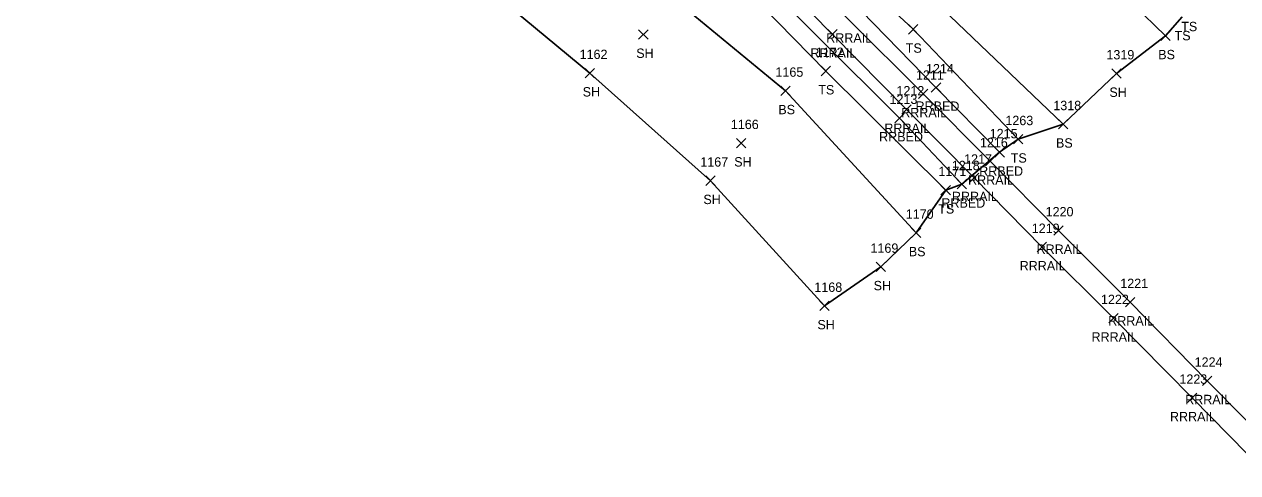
# Model space of a CAD drawing. Extents: x 1679360 to 1685861, y 903420 to 905946.
# Drawn here: x 1679830.3 to 1680089.3, y 903736.5 to 903832.2 of the extents above; entities that cross this region are included whole.
import ezdxf

# ---------------------------------------------------------------- set-up
doc = ezdxf.new("R2010")
doc.units = 0
for name, color, linetype in [('L_A', 7, 'Continuous'), ('L_I', 7, 'Continuous'), ('L_TIC', 7, 'Continuous'), ('LELB', 7, 'Continuous'), ('LSOGP', 7, 'Continuous'), ('R_A', 7, 'Continuous'), ('R_I', 7, 'Continuous'), ('R_TIC', 7, 'Continuous'), ('RR', 7, 'Continuous'), ('RRB', 7, 'Continuous')]:
    doc.layers.add(name, color=color, linetype=linetype)

msp = doc.modelspace()

# ---------------------------------------------------------------- linework, layer by layer
at = {"layer": 'L_TIC'}
for points in [[(1679961.47, 903829.04), (1679963.47, 903831.04)], [(1679963.47, 903829.04), (1679961.47, 903831.04)], [(1680019.07, 903830.14), (1680021.07, 903832.14)], [(1680021.07, 903830.14), (1680019.07, 903832.14)], [(1680072.91, 903828.75), (1680074.91, 903830.75)], [(1680074.91, 903828.75), (1680072.91, 903830.75)], [(1680000.4, 903821.24), (1680002.4, 903823.24)], [(1680002.4, 903821.24), (1680000.4, 903823.24)], [(1679950.04, 903820.8), (1679952.04, 903822.8)], [(1679952.04, 903820.8), (1679950.04, 903822.8)], [(1680062.45, 903820.72), (1680064.45, 903822.72)], [(1680064.45, 903820.72), (1680062.45, 903822.72)], [(1679991.84, 903817.01), (1679993.84, 903819.01)], [(1679993.84, 903817.01), (1679991.84, 903819.01)], [(1680051.1, 903809.88), (1680053.1, 903811.88)], [(1680053.1, 903809.88), (1680051.1, 903811.88)], [(1679982.38, 903805.85), (1679984.38, 903807.85)], [(1679984.38, 903805.85), (1679982.38, 903807.85)], [(1680041.48, 903806.68), (1680043.48, 903808.68)], [(1680043.48, 903806.68), (1680041.48, 903808.68)], [(1679975.8, 903797.83), (1679977.8, 903799.83)], [(1679977.8, 903797.83), (1679975.8, 903799.83)], [(1680026, 903795.8), (1680028, 903797.8)], [(1680028, 903795.8), (1680026, 903797.8)], [(1680019.69, 903786.69), (1680021.69, 903788.69)], [(1680021.69, 903786.69), (1680019.69, 903788.69)], [(1680012.13, 903779.43), (1680014.13, 903781.43)], [(1680014.13, 903779.43), (1680012.13, 903781.43)], [(1680000.15, 903771.09), (1680002.15, 903773.09)], [(1680002.15, 903771.09), (1680000.15, 903773.09)]]:
    msp.add_lwpolyline(points, dxfattribs=at)
at = {"layer": 'LELB'}
for points in [[(1680042.48, 903807.68), (1680020.07, 903831.14), (1679994.57, 903854.85), (1679973.52, 903877.19), (1679947.49, 903902.98), (1679918.08, 903936.81), (1679895.51, 903960.77), (1679875.1, 903984.26)], [(1679894.89, 903975.93), (1679910.27, 903960.99), (1679935.15, 903935.63), (1679969.34, 903902.55), (1679995.86, 903870.36), (1680023.14, 903838.66), (1680052.1, 903810.88)], [(1679854.83, 903964.92), (1679872.81, 903942.29), (1679891.12, 903918.82), (1679918.93, 903890.39), (1679939.76, 903869.14), (1679968.6, 903838.01), (1679992.84, 903818.01), (1680020.69, 903787.69)], [(1680027, 903796.8), (1680001.4, 903822.24), (1679984.38, 903839.7), (1679957.18, 903867.74), (1679928.2, 903894.12), (1679909.11, 903915.88), (1679887.98, 903941.49), (1679868.32, 903960.05)], [(1680073.91, 903829.75), (1680039.44, 903863.28), (1680011.71, 903891.77), (1679980.2, 903922.91), (1679955.89, 903942.39), (1679970.51, 903943.92), (1679984.54, 903937.24)]]:
    msp.add_lwpolyline(points, dxfattribs=at)
at = {"layer": 'LSOGP'}
msp.add_lwpolyline([(1679920.81, 903846.9), (1679951.04, 903821.8), (1679976.8, 903798.83), (1680001.15, 903772.09), (1680013.13, 903780.43), (1680020.69, 903787.69), (1680027, 903796.8), (1680030.44, 903798.07), (1680038.52, 903804.88), (1680042.48, 903807.68), (1680052.1, 903810.88), (1680063.45, 903821.72), (1680073.91, 903829.75), (1680077.44, 903833.8)], dxfattribs=at)
at = {"layer": 'R_TIC'}
for points in [[(1680001.83, 903829.07), (1680003.83, 903831.07)], [(1680003.83, 903829.07), (1680001.83, 903831.07)], [(1680021.22, 903816.37), (1680023.22, 903818.37)], [(1680023.22, 903816.37), (1680021.22, 903818.37)], [(1680023.93, 903817.74), (1680025.93, 903819.74)], [(1680025.93, 903817.74), (1680023.93, 903819.74)], [(1680016.14, 903811.2), (1680018.14, 903813.2)], [(1680018.14, 903811.2), (1680016.14, 903813.2)], [(1680017.62, 903813.03), (1680019.62, 903815.03)], [(1680019.62, 903813.03), (1680017.62, 903815.03)], [(1680037.52, 903803.88), (1680039.52, 903805.88)], [(1680039.52, 903803.88), (1680037.52, 903805.88)], [(1680035.49, 903801.97), (1680037.49, 903803.97)], [(1680037.49, 903801.97), (1680035.49, 903803.97)], [(1680032.05, 903798.46), (1680034.05, 903800.46)], [(1680034.05, 903798.46), (1680032.05, 903800.46)], [(1680029.44, 903797.07), (1680031.44, 903799.07)], [(1680031.44, 903797.07), (1680029.44, 903799.07)], [(1680050.11, 903787.21), (1680052.11, 903789.21)], [(1680052.11, 903787.21), (1680050.11, 903789.21)], [(1680046.5, 903783.67), (1680048.5, 903785.67)], [(1680048.5, 903783.67), (1680046.5, 903785.67)], [(1680065.39, 903771.91), (1680067.39, 903773.91)], [(1680067.39, 903771.91), (1680065.39, 903773.91)], [(1680061.83, 903768.48), (1680063.83, 903770.48)], [(1680063.83, 903768.48), (1680061.83, 903770.48)], [(1680081.82, 903755.11), (1680083.82, 903757.11)], [(1680083.82, 903755.11), (1680081.82, 903757.11)], [(1680078.58, 903751.46), (1680080.58, 903753.46)], [(1680080.58, 903751.46), (1680078.58, 903753.46)]]:
    msp.add_lwpolyline(points, dxfattribs=at)
at = {"layer": 'RR'}
for points in [[(1679824.64, 904028.72), (1679837.34, 904012.39), (1679861.93, 903982.57), (1679878.2, 903963.7), (1679892.43, 903947.81), (1679907.95, 903930.19), (1679922.38, 903914.41), (1679937.85, 903897.68), (1679952.05, 903882.52), (1679968.97, 903864.98), (1679984.51, 903848.78), (1680002.83, 903830.07), (1680018.62, 903814.03), (1680033.05, 903799.46), (1680047.5, 903784.67), (1680062.83, 903769.48), (1680079.58, 903752.46), (1680095.32, 903736.48)], [(1679831.29, 904028.45), (1679844.1, 904012.06), (1679865.83, 903985.59), (1679882.11, 903966.82), (1679896.05, 903950.91), (1679911.54, 903933.69), (1679925.87, 903917.93), (1679941.58, 903900.91), (1679955.49, 903886.24), (1679972.28, 903868.6), (1679988.05, 903852.2), (1680006.22, 903833.3), (1680022.22, 903817.37), (1680036.49, 903802.97), (1680051.11, 903788.21), (1680066.39, 903772.91), (1680082.82, 903756.11), (1680099.28, 903739.48)]]:
    msp.add_lwpolyline(points, dxfattribs=at)
at = {"layer": 'RRB'}
for points in [[(1679852.8, 904005.56), (1679867.15, 903987.02), (1679898.43, 903952.3), (1679928.17, 903919.5), (1679957.86, 903886.73), (1679990.5, 903854.15), (1680024.93, 903818.74), (1680038.52, 903804.88)], [(1679840.74, 904004.22), (1679860.45, 903979.99), (1679889.94, 903946.25), (1679920.7, 903912.73), (1679950.15, 903880.79), (1679982.32, 903846.88), (1680017.14, 903812.2), (1680030.44, 903798.07)]]:
    msp.add_lwpolyline(points, dxfattribs=at)

# ---------------------------------------------------------------- texts
at = {"layer": 'L_A'}
for s, p in [('TS', (1680075.85, 903828.8)), ('TS', (1680077.27, 903830.74)), ('SH', (1679960.96, 903825.04)), ('TS', (1680018.48, 903826.14)), ('BS', (1680072.36, 903824.75)), ('SH', (1679949.53, 903816.8)), ('TS', (1679999.81, 903817.24)), ('SH', (1680061.94, 903816.72)), ('BS', (1679991.28, 903813.01)), ('BS', (1680050.54, 903805.88)), ('SH', (1679981.87, 903801.85)), ('TS', (1680040.89, 903802.68)), ('SH', (1679975.29, 903793.83)), ('TS', (1680025.41, 903791.8)), ('BS', (1680019.13, 903782.69)), ('SH', (1680011.62, 903775.43)), ('SH', (1679999.63, 903767.09))]:
    msp.add_text(s, height=2, dxfattribs=at).set_placement(p)
at = {"layer": 'L_I'}
for s, p in [('1162', (1679948.87, 903824.8)), ('1172', (1679999.27, 903825.24)), ('1319', (1680061.31, 903824.72)), ('1165', (1679990.67, 903821.01)), ('1318', (1680049.97, 903813.88)), ('1263', (1680039.74, 903810.68)), ('1166', (1679981.15, 903809.85)), ('1167', (1679974.63, 903801.83)), ('1171', (1680025.44, 903799.8)), ('1170', (1680018.48, 903790.69)), ('1169', (1680010.95, 903783.43)), ('1168', (1679998.97, 903775.09))]:
    msp.add_text(s, height=2, dxfattribs=at).set_placement(p)
at = {"layer": 'R_A'}
for s, p in [('RRRAIL', (1680001.51, 903828.3)), ('RRRAIL', (1679998.13, 903825.07)), ('RRBED', (1680020.57, 903813.74)), ('RRRAIL', (1680017.51, 903812.37)), ('RRRAIL', (1680013.91, 903809.03)), ('RRBED', (1680012.79, 903807.2)), ('RRRAIL', (1680031.78, 903797.97)), ('RRBED', (1680034.16, 903799.88)), ('RRBED', (1680026.09, 903793.07)), ('RRRAIL', (1680028.34, 903794.46)), ('RRRAIL', (1680046.4, 903783.21)), ('RRRAIL', (1680042.79, 903779.67)), ('RRRAIL', (1680061.68, 903767.91)), ('RRRAIL', (1680058.12, 903764.48)), ('RRRAIL', (1680078.11, 903751.11)), ('RRRAIL', (1680074.87, 903747.46))]:
    msp.add_text(s, height=2, dxfattribs=at).set_placement(p)
at = {"layer": 'R_I'}
for s, p in [('1214', (1680022.8, 903821.74)), ('1211', (1680020.66, 903820.37)), ('1212', (1680016.49, 903817.03)), ('1213', (1680015.01, 903815.2)), ('1216', (1680034.31, 903805.97)), ('1215', (1680036.39, 903807.88)), ('1218', (1680028.31, 903801.07)), ('1217', (1680030.93, 903802.46)), ('1220', (1680048.33, 903791.21)), ('1219', (1680045.37, 903787.67)), ('1221', (1680064.26, 903775.91)), ('1222', (1680060.14, 903772.48)), ('1224', (1680080.13, 903759.11)), ('1223', (1680076.88, 903755.46))]:
    msp.add_text(s, height=2, dxfattribs=at).set_placement(p)

doc.saveas('drawing.dxf')
